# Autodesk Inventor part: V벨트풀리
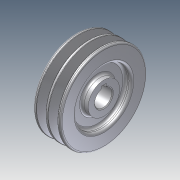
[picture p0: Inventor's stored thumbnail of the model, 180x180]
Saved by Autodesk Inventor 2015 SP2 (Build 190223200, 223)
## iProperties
Company: 한국ATC센터
Created: 2015-02
Part Number: V벨트풀리
Document SubType Name: Modeling
Designer: KYOUNG IL JANG
Density: 1 g/cm^3
Material: 일반
Appearance: 기본값
Author: KYOUNG IL JANG
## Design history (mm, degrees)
sketch "스케치1"
  geometry: L1 (0, 0)-(35, 0); L2 (35, 0)-(35, 55); L3 (35, 55)-(31.062, 55); L4 (31.062, 55)-(27.001, 42.5); L5 (27.001, 42.5)-(22.999, 42.5); L6 (22.999, 42.5)-(18.938, 55); L7 (18.938, 55)-(16.062, 55); L8 (16.062, 55)-(12.001, 42.5); L9 (12.001, 42.5)-(7.999, 42.5); L10 (7.999, 42.5)-(3.938, 55); L11 (3.938, 55)-(0, 55); L12 (0, 55)-(0, 0); L13 (5.4, 50.5)-(14.6, 50.5); L14 (20.4, 50.5)-(29.6, 50.5); 3 further points
  constraints: 28 end point, 8 parallel, 6 collinear, 4 point on line, 3 midpoint, 2 perpendicular, 1 horizontal, 1 vertical alignment
  dimensions: "d0" = 36 deg angle of L8 L10; "d1" = 9.2 distance of L14.start L14.end; "d2" = 4.5 distance between parallel lines of L13 L11; "d3" = 8 distance between parallel lines of L9 L13; "d4" = 10 distance from line of point (25, 42.5) L2; "d5" = 15 distance of point (25, 42.5) point (10, 42.5); "d6" = 35 distance of L1.start L1.end; "d7" = 101 diameter of L14 L1
revolve "회전1" sketch "스케치1" stored, may be unused: angle "d8" = 90 deg
fillet "모깎기1" dims "d9" = 2
fillet "모깎기2" dims "d10" = 0.5
fillet "모깎기3" dims "d11" = 1
sketch "스케치2"
  geometry: L1 (0, 0)-(8, 0); L2 (8, 0)-(8, 20); L3 (8, 20)-(17, 20); L4 (17, 20)-(17, 35); L5 (17, 35)-(0, 35); L6 (0, 35)-(0, 0); L7 (35, 35)-(27, 35); L8 (27, 35)-(27, 20); L9 (27, 20)-(35, 20); L10 (35, 20)-(35, 35); L11 (35, 53)-(35, -53) reference
  constraints: 20 end point, 6 parallel, 3 collinear, 3 perpendicular, 1 horizontal
  dimensions: "d12" = 40 diameter of L9 L1; "d13" = 70 diameter of L7 L1; "d14" = 8 distance between parallel lines of L10 L8; "d15" = 10 distance between parallel lines of L8 L4; "d16" = 9 distance between parallel lines of L4 L2
revolve "회전2" sketch "스케치2" stored, may be unused: angle "d17" = 90 deg
hole "구멍1" diameter "d20" = 22; stored, may be unused: countersink angle "d24" = 90 deg, drill point angle "d26" = 118 deg; dims "d18" = 10, "d19" = 10, "d21" = 6, "d22" = 4, "d23" = 2, "d25" = 8
sketch "스케치3"
  geometry: L1 (-14.8, -3)-(-7.8, -3); L2 (-7.8, -3)-(-7.8, 3); L3 (-7.8, 3)-(-14.8, 3); L4 (-14.8, 3)-(-14.8, -3); C1 r 11 at (0, 0) reference; 2 further points
  constraints: 8 end point, 2 parallel, 1 horizontal, 1 horizontal alignment, 1 midpoint, 1 perpendicular
  dimensions: "d27" = 25.8 dimension on C1 L4; "d28" = 6 distance of L3.end L1.start; "d29" = 7 distance between parallel lines of L4 L2
extrude "돌출1" cut sketch "스케치3" stored distance "d30" = 10; taper "d31" = 0 deg
fillet "모깎기4" dims "d32" = 3
chamfer "모따기1" distance "d33" = 1; stored, may be unused: second distance "d34" = 2, angle "d35" = 45 deg
node "솔리드1"
